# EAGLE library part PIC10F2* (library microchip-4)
uPC nW 0,25/0,5k Program Flash memory Comparator
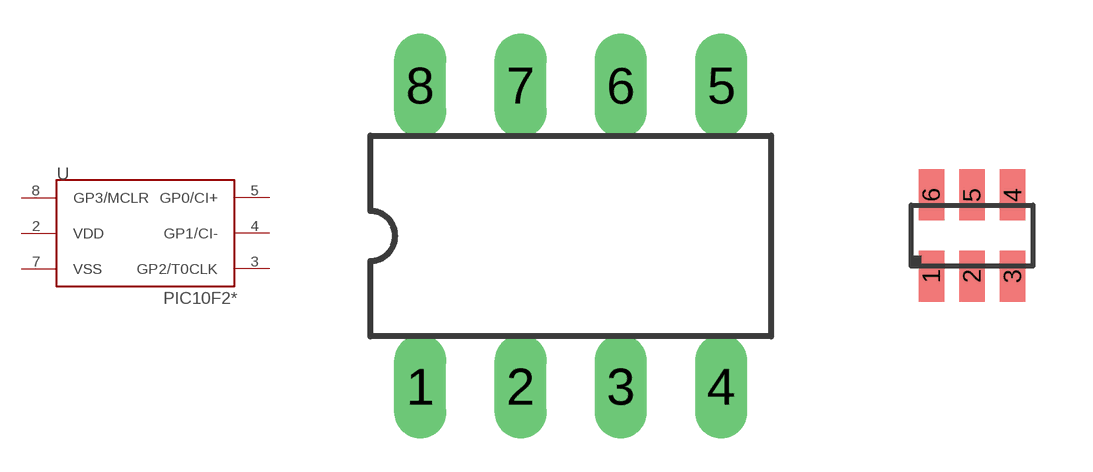
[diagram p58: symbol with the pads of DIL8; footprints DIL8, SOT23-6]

Designator prefix -

## PIC10F204P, PIC10F206P  [DIL8]
2  VDD  pwr
3  GP2/T0CLK
4  GP1/CI-
5  GP0/CI+
7  VSS  pwr
8  GP3/MCLR  in

## PIC10F202OT, PIC10F204OT  [SOT23-6]
1  GP0/CI+
2  VSS  pwr
3  GP1/CI-
4  GP2/T0CLK
5  VDD  pwr
6  GP3/MCLR  in

## Footprint DIL8 (pad centres in mm)
Dual In Line package type P
drill 0.813 long: 1 -3.81,-3.81; 2 -1.27,-3.81; 3 1.27,-3.81; 4 3.81,-3.81; 5 3.81,3.81; 6 1.27,3.81; 7 -1.27,3.81; 8 -3.81,3.81

## Footprint SOT23-6 (pad centres in mm)
SMD 3x1,75mm /6pin
smd 0.635 x 1.27: 1 -1.016,-1.016; 2 0,-1.016; 3 1.016,-1.016; 4 1.016,1.016; 5 0,1.016; 6 -1.016,1.016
